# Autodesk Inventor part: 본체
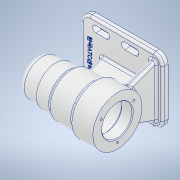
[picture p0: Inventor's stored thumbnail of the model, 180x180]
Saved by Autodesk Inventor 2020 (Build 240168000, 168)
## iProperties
Created: 2021-10
Part Number: 본체
Material: 알루미늄 6061
Document SubType Name: Modeling
Designer: user
Density: 2.7 g/cm^3
Appearance: 알루미늄 - 평지
Mass: 691.173 g
Surface Area: 699.007 cm^2
Volume: 255.99 cm^3
Author: user
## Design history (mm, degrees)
sketch "스케치1"
  geometry: L1 (-56, -45)-(56, -45); L2 (56, -45)-(56, 45); L3 (56, 45)-(-56, 45); L4 (-56, 45)-(-56, -45); L5 (-56, -45)-(56, 45); L6 (56, -45)-(-56, 45); 1 further point
  constraints: 12 end point, 2 midpoint, 2 parallel, 1 horizontal, 1 perpendicular
  dimensions: "d0" = 112 distance of L2.end L3.end; "d1" = 90 distance of L3.end L1.start
extrude "돌출1" new body sketch "스케치1" distance "d2" = 8; taper "d3" = 0 deg
sketch "스케치2"
  geometry: L1 (62.238, 70)-(-57.921, 70); L2 (10, 100)-(10, 97); L3 (10, 97)-(32, 97); L4 (32, 97)-(32, 95); L5 (56, 95)-(56, 70); L6 (50, 70)-(50, 77.5); L7 (47, 80.5)-(47, 80.5); L8 (47, 80.5)-(47, 85.7); L9 (46.7, 86)-(43, 86); L10 (43, 86)-(43, 87.2); L11 (25, 87.5)-(25, 90.7); L12 (24.7, 91)-(13, 91); L13 (13, 91)-(13, 91); L14 (10, 94)-(-38, 94); L15 (-41, 91)-(-41, 91); L16 (-41, 91)-(-56, 91); L17 (-56, 0)-(-56, 8) reference; L18 (10, 100)-(-24, 100); L19 (-24, 100)-(-24, 104); L20 (-24, 104)-(-56, 104); L21 (-56, 104)-(-56, 91); L22 (42.7, 87.5)-(25, 87.5); L23 (56, 95)-(32, 95); A1 r 0.3 centre (46.7, 85.7) between (47, 85.7) and (46.7, 86); A2 r 0.3 centre (42.7, 87.2) between (43, 87.2) and (42.7, 87.5); A3 r 0.3 centre (24.7, 90.7) between (25, 90.7) and (24.7, 91); A4 r 3 centre (47, 77.5) between (50, 77.5) and (47, 80.5); A5 r 3 centre (10, 91) between (13, 91) and (10, 94); A6 r 3 centre (-38, 91) between (-38, 94) and (-41, 91); 5 further points
  constraints: 44 end point, 13 perpendicular, 12 point on circle, 12 tangent, 6 centre point, 4 equal radius, 4 point on line, 3 horizontal, 1 vertical
  dimensions: "d4" = 70 distance from line of point (0, 0) L1; "d5" = 120.15879 distance of L1.start L1.end; "d8" = 24 distance between parallel lines of L4 L5; "d9" = 46 distance between parallel lines of L2 L5; "d10" = 112 distance between parallel lines of L21 L5; "d11" = 80 distance between parallel lines of L19 L5; "d12" = 15 distance between parallel lines of L15 L21; "d14" = 6 distance between parallel lines of L6 L5; "d15" = 3 distance between parallel lines of L8 L6; "d16" = 4 distance from line of L9.end L8; "d17" = 18 distance from line of L11 L9.end; "d18" = 12 distance from line of point (13, 94) L11; "d19" = 42 diameter of L16 L1; "d20" = 48 diameter of L14 L1; "d21" = 21 diameter of L7 L1; "d22" = 32 diameter of L9 L1; "d23" = 35 diameter of L22 L1; "d24" = 42 diameter of L12 L1; "d25" = 50 diameter of L23 L1; "d26" = 54 diameter of L3 L1; "d27" = 60 diameter of L18 L1; "d28" = 68 diameter of L20 L1; "d29" = 56 distance from line of point (0, 0) L5; "d30" = 0.3 radius of A1; "d31" = 3 radius of A4
revolve "회전1" sketch "스케치2" stored, may be unused: angle "d32" = 90 deg
sketch "스케치4"
  geometry: L1 (-29, 4)-(48, 4); L2 (48, 4)-(48, -4); L3 (48, -4)-(-29, -4); L4 (-29, -4)-(-29, 4); L5 (-29, 4)-(48, -4); L6 (48, 4)-(-29, -4); L7 (56, -45)-(56, 45) reference; 2 further points
  constraints: 12 end point, 2 midpoint, 2 parallel, 1 horizontal, 1 perpendicular
  dimensions: "d34" = 8 distance between parallel lines of L7 L2; "d35" = 77 distance of L2.end L3.end; "d36" = 8 distance of L1.end L2.end; "d37" = 0 vertical distance of point (0, 0) point (9.5, 0)
extrude "돌출2" join sketch "스케치4" stored distance "d38" = 8; taper "d39" = 0 deg
sketch "스케치5"
  geometry: L1 (0, 49)-(0, -41) reference; L2 (0, -33)-(-37.342, -19.409); L3 (0, 41)-(-37.342, 27.409); A1 r 34 centre (-62, 4) between (-28.236, 8) and (-28.236, 0) reference; 1 further point
  constraints: 4 end point, 2 point on circle, 2 point on line
  dimensions: "d40" = 8 distance of L1.end L2.start; "d41" = 8 distance of L1.start L3.start; "d42" = 110 deg angle of L1 L2; "d43" = 110 deg angle of L1 L3
feature "리브1" sketch "스케치5" dims "d44" = 1, "d45" = 8, "d46" = 0, "d47" = 0, "d48" = 1, "d49" = 1
sketch "스케치6"
  geometry: L1 (28.236, 41)-(28.236, -49) reference; L2 (28.236, 33)-(-9.106, 19.409); A1 r 34 centre (-33.764, -4) between (0, 0) and (0, -8) reference; 1 further point
  constraints: 2 end point, 1 point on circle, 1 point on line
  dimensions: "d50" = 8 distance of L1.start L2.start; "d51" = 110 deg angle of L1 L2
feature "리브2" sketch "스케치6" dims "d52" = 1, "d53" = 8, "d54" = 0, "d55" = 0, "d56" = 1, "d57" = 1
feature "면 기울기1" dims angle "d59" = 15 deg
sketch "스케치8"
  geometry: L1 (-40.5, 33)-(-16.5, 33); L2 (-36, 28.5)-(-21, 28.5); L3 (-21, 37.5)-(-36, 37.5); L4 (-56, 45)-(-56, -45) reference; L5 (-0.5, 33)-(23.5, 33); L6 (4, 28.5)-(19, 28.5); L7 (19, 37.5)-(4, 37.5); A1 r 4.5 centre (-36, 33) between (-36, 37.5) and (-36, 28.5); A2 r 4.5 centre (-21, 33) between (-21, 28.5) and (-21, 37.5); A3 r 4.5 centre (4, 33) between (4, 37.5) and (4, 28.5); A4 r 4.5 centre (19, 33) between (19, 28.5) and (19, 37.5); 3 further points
  constraints: 16 end point, 12 point on circle, 8 tangent, 4 centre point, 4 point on line, 2 horizontal, 2 midpoint, 2 parallel
  dimensions: "d60" = 9 diameter of A2; "d61" = 15 distance of A2.centre A1.centre; "d63" = 33 vertical distance of point (0, 0) point (-28.5, 33); "d64" = 9 diameter of A4; "d65" = 15 distance of A4.centre A3.centre; "d66" = 25 distance of A2.centre A3.centre; "d67" = 33 vertical distance of point (0, 0) point (11.5, 33); "d98" = 20 distance from line of A1.centre L4
extrude "돌출3" cut sketch "스케치8" distance "d68" = 20; taper "d69" = 0 deg
sketch "스케치9"
  geometry: L1 (-56, 45)-(-56, -45) reference; A1 r 4.5 centre (-36, 33) between (-36, 37.5) and (-36, 28.5) reference; 2 further points
  constraints: 1 other
  dimensions: "d70" = 12 distance from line of L1 point (-44, 0); "d71" = 33 vertical distance of point (-44, 0) A1.centre
feature "엠보싱1" sketch "스케치9" dims "d0" = 112, "d1" = 90, "d4" = 70, "d5" = 120.15879, "d8" = 24, "d9" = 46, "d10" = 112, "d11" = 80, "d12" = 15, "d14" = 6, "d15" = 3, "d16" = 4, "d17" = 18, "d18" = 12, "d19" = 42, "d20" = 48, "d21" = 21, "d22" = 32, "d23" = 35, "d24" = 42, "d25" = 50, "d26" = 54, "d27" = 60, "d28" = 68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
sketch "스케치10"
  geometry: L1 (0, 0)-(-22.517, 13); L2 (0, 0)-(0, -26); C1 r 34 at (0, 0) reference; C2 r 7.5 at (0, 0) reference; A1 r 26 centre (0, 0) between (0, -26) and (-22.517, 13); 2 further points
  constraints: 4 end point, 2 coincident, 2 point on circle, 1 centre point, 1 vertical
  dimensions: "d74" = 52 diameter of A1; "d75" = 120 deg angle of L2 L1
hole "구멍1" sketch "스케치10" at (-22.517, 13) diameter "d76" = 3.242; stored, may be unused: countersink angle "d80" = 90 deg, drill point angle "d82" = 118 deg; dims "d77" = 8, "d78" = 4, "d79" = 2, "d81" = 11
fillet "모깎기1" dims "d86" = 8
fillet "모깎기2" dims "d87" = 12
fillet "모깎기3" dims "d88" = 3
fillet "모깎기4" dims "d89" = 3
fillet "모깎기5" dims "d90" = 3
fillet "모깎기6" dims "d91" = 3
chamfer "모따기1" distance "d92" = 1; stored, may be unused: second distance "d93" = 2, angle "d94" = 45 deg
fillet "모깎기7" dims "d95" = 3
fillet "모깎기8" dims "d96" = 3
fillet "모깎기9" dims "d97" = 3
node "솔리드1"
mirror "미러1"
pattern_circular "원형 패턴1" dims angle "d84" = 360 deg
feature "A9D066F2-1C7D-4E18-AEED-F7BC21143FA4" dims "d76" = 3.242, "d77" = 8, "d78" = 4, "d79" = 2, "d80" = 90 deg, "d81" = 11, "d82" = 118 deg
